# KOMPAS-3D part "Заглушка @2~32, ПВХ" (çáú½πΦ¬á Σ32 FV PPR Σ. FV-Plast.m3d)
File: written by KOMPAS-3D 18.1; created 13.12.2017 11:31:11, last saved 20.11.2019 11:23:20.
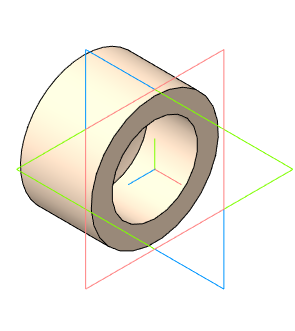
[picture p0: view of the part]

Document properties: Автор: Милов; Организация: Милов; Полное имя файла: D:\1 ПКИ 3D\Полипропиленовые фитинги, трубы\Заглушка ф32 FV PPR ф. FV-Plast.m3d

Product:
- Part/product: Заглушка @2~32  | designation ПВХ
    Материал: Полипропилен  ГОСТ 26996-86 (density 900 kg/m3)
    Масса: 0.0281994
    Раздел спецификации: Прочие изделия
- Part/product: Заглушка @2~32 FV PPR ф. "FV-Plast"
    Материал: Полипропилен  ГОСТ 26996-86 (density 900 kg/m3)
    Масса: 0.0281994
    Раздел спецификации: Прочие изделия

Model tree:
1. Эскиз:1
2. Операция вращения:1  (labels: Полипропилен  ГОСТ 26996-86)
     Угол 1 = 360

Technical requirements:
  Gost Type A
